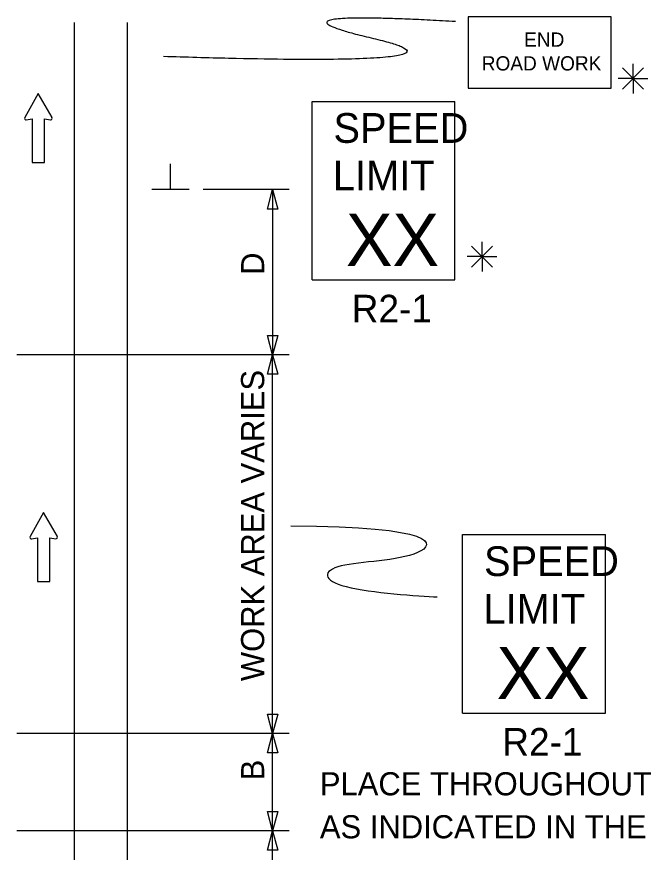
# Model space of a CAD drawing. Extents: x 16576 to 19508, y 5728 to 6974.
# Drawn here: x 18016.2 to 18207.5, y 6670.3 to 6923 of the extents above; entities that cross this region are included whole.
import ezdxf

# ---------------------------------------------------------------- set-up
doc = ezdxf.new("R2010")
doc.units = 0
for name, color, linetype in [('MT_SCRATCH_LEVEL_E', 7, 'Continuous'), ('PAVT_EDGE_EX', 7, 'Continuous'), ('TRAFFIC_SIGNS_PR', 7, 'Continuous'), ('TYPICAL_TEXT_DIMEN_PR', 7, 'Continuous')]:
    doc.layers.add(name, color=color, linetype=linetype)

msp = doc.modelspace()

# ---------------------------------------------------------------- linework, layer by layer
at = {"layer": 'MT_SCRATCH_LEVEL_E'}
for p, q in [((18022.77, 6899.76), (18018.65, 6892.52)), ((18026.91, 6892.52), (18022.77, 6899.76)), ((18019.14, 6891.84), (18020.91, 6892.15)), ((18020.91, 6892.15), (18020.91, 6878.9)), ((18024.66, 6878.9), (18024.66, 6892.15)), ((18024.66, 6892.15), (18026.43, 6891.84)), ((18020.91, 6878.9), (18024.66, 6878.9)), ((18024.38, 6773.03), (18020.27, 6765.79)), ((18028.53, 6765.79), (18024.38, 6773.03)), ((18020.75, 6765.1), (18022.53, 6765.42)), ((18022.53, 6765.42), (18022.53, 6752.16)), ((18026.27, 6752.16), (18026.27, 6765.42)), ((18026.27, 6765.42), (18028.05, 6765.1)), ((18022.53, 6752.16), (18026.27, 6752.16))]:
    msp.add_line(p, q, dxfattribs=at)
for centre, start, end in [((18019.06, 6892.3), 150.4248, 279.9638), ((18026.5, 6892.3), 260.0362, 29.7731), ((18020.68, 6765.56), 150.4248, 279.9638), ((18028.12, 6765.57), 260.0362, 29.7731)]:
    msp.add_arc(centre, 0.463, start, end, dxfattribs=at)
at = {"layer": 'PAVT_EDGE_EX'}
for p, q in [((18033.63, 6921.33), (18033.63, 5988.51)), ((18049.63, 6921.33), (18049.63, 5988.51))]:
    msp.add_line(p, q, dxfattribs=at)
at = {"layer": 'TRAFFIC_SIGNS_PR'}
for p, q in [((18105.54, 6897.41), (18148.74, 6897.41)), ((18105.54, 6843.41), (18105.54, 6897.41)), ((18148.74, 6843.41), (18148.74, 6897.41)), ((18105.54, 6843.41), (18148.74, 6843.41)), ((18151.07, 6766.35), (18194.27, 6766.35)), ((18151.07, 6712.35), (18151.07, 6766.35)), ((18194.27, 6712.35), (18194.27, 6766.35)), ((18151.07, 6712.35), (18194.27, 6712.35))]:
    msp.add_line(p, q, dxfattribs=at)
msp.add_lwpolyline([(18152.81, 6901.44), (18196.01, 6901.44), (18196.01, 6923.04), (18152.81, 6923.04)], close=True, dxfattribs=at)
msp.add_open_spline([(18148.92, 6921.54), (18086.6, 6925.24), (18161.65, 6907.71), (18060.63, 6910.98)], degree=2, dxfattribs=at)
at = {"layer": 'TYPICAL_TEXT_DIMEN_PR'}
for p, q in [((18202.65, 6904.34), (18202.65, 6908.8)), ((18199.47, 6907.53), (18205.84, 6901.15)), ((18205.84, 6907.53), (18199.47, 6901.15)), ((18202.65, 6904.34), (18198.12, 6904.34)), ((18202.65, 6904.34), (18205.84, 6904.34)), ((18202.65, 6904.34), (18207.13, 6904.34)), ((18202.65, 6904.34), (18202.65, 6899.84)), ((18062.76, 6870.72), (18062.76, 6878.51)), ((18068.38, 6870.72), (18057.13, 6870.72)), ((18098.63, 6870.72), (18072.63, 6870.72)), ((18092.06, 6864.86), (18093.63, 6870.72)), ((18093.63, 6870.72), (18093.63, 6820.72)), ((18093.63, 6870.72), (18095.2, 6864.86)), ((18093.63, 6864.86), (18092.06, 6864.86)), ((18095.2, 6864.86), (18093.63, 6864.86)), ((18153.78, 6853.65), (18160.15, 6847.28)), ((18160.15, 6853.65), (18153.78, 6847.28)), ((18156.97, 6850.47), (18156.97, 6854.92)), ((18156.97, 6850.47), (18152.43, 6850.47)), ((18156.97, 6850.47), (18160.15, 6850.47)), ((18156.97, 6850.47), (18161.44, 6850.47)), ((18156.97, 6850.47), (18156.97, 6845.97)), ((18093.63, 6820.72), (18092.06, 6826.58)), ((18092.06, 6826.58), (18093.63, 6826.58)), ((18093.63, 6826.58), (18095.2, 6826.58)), ((18095.2, 6826.58), (18093.63, 6820.72)), ((18098.63, 6820.72), (18016.24, 6820.72)), ((18092.06, 6814.86), (18093.63, 6820.72)), ((18093.63, 6706.19), (18093.63, 6820.72)), ((18093.63, 6820.72), (18095.2, 6814.86)), ((18093.63, 6814.86), (18092.06, 6814.86)), ((18095.2, 6814.86), (18093.63, 6814.86)), ((18093.63, 6706.19), (18092.06, 6712.05)), ((18092.06, 6712.05), (18093.63, 6712.05)), ((18093.63, 6712.05), (18095.2, 6712.05)), ((18095.2, 6712.05), (18093.63, 6706.19)), ((18098.63, 6706.19), (18016.24, 6706.19)), ((18092.06, 6700.32), (18093.63, 6706.19)), ((18093.63, 6676.76), (18093.63, 6706.19)), ((18093.63, 6706.19), (18095.2, 6700.32)), ((18093.63, 6700.32), (18092.06, 6700.32)), ((18095.2, 6700.32), (18093.63, 6700.32)), ((18093.63, 6676.76), (18092.06, 6682.62)), ((18092.06, 6682.62), (18093.63, 6682.62)), ((18093.63, 6682.62), (18095.2, 6682.62)), ((18095.2, 6682.62), (18093.63, 6676.76)), ((18098.63, 6676.76), (18016.24, 6676.76)), ((18092.06, 6670.9), (18093.63, 6676.76)), ((18093.63, 6646.19), (18093.63, 6676.76)), ((18093.63, 6676.76), (18095.2, 6670.9)), ((18093.63, 6670.9), (18092.06, 6670.9)), ((18095.2, 6670.9), (18093.63, 6670.9))]:
    msp.add_line(p, q, dxfattribs=at)
msp.add_open_spline([(18099.12, 6769.05), (18143.49, 6768.75), (18143.15, 6758.31), (18108.57, 6758.31), (18108.57, 6749.64), (18137.89, 6747.77), (18143.43, 6747.51)], degree=3, dxfattribs=at)

# ---------------------------------------------------------------- texts
at = {"layer": 'TRAFFIC_SIGNS_PR'}
for s, height, p in [('END', 4.31, (18169.69, 6913.96)), ('ROAD WORK', 4.31, (18156.87, 6906.77)), ('SPEED', 9, (18112.03, 6884.88)), ('LIMIT', 9, (18111.85, 6870.48)), ('XX', 15.785, (18115.8, 6847.64)), ('R2-1', 8.37, (18117.55, 6830.54)), ('SPEED', 9, (18157.56, 6753.82)), ('LIMIT', 9, (18157.38, 6739.42)), ('XX', 15.785, (18161.32, 6716.58)), ('R2-1', 8.37, (18163.08, 6699.48)), ('PLACE THROUGHOUT WORK AREA', 7, (18107.93, 6687.48)), ('AS INDICATED IN THE NOTES.', 7, (18107.93, 6674.48))]:
    msp.add_text(s, height=height, dxfattribs=at).set_placement(p)
at = {"layer": 'TYPICAL_TEXT_DIMEN_PR'}
for s, p in [('D', (18091.08, 6844.94)), ('WORK AREA VARIES', (18091.08, 6722.04)), ('B', (18091.08, 6692.02))]:
    msp.add_text(s, height=7, rotation=90, dxfattribs=at).set_placement(p)

doc.saveas('drawing.dxf')
